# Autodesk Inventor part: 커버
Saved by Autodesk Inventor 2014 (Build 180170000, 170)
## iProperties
Created: 2025-06
Part Number: 커버
Material: 알루미늄 6061
Document SubType Name: Modeling
Designer: dg
Density: 2.71 g/cm^3
Appearance: 알루미늄 - 평지
Mass: 74.4778 g
Surface Area: 107.152 cm^2
Volume: 27.4826 cm^3
Author: jhkim
Creation Date: 2025-05-27
Sending System: Autodesk Inventor 2026
Preprocessor: ST-DEVELOPER v20.1
Author: dg
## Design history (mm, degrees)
node "커버1"
node "솔리드1"
node "기준1"
